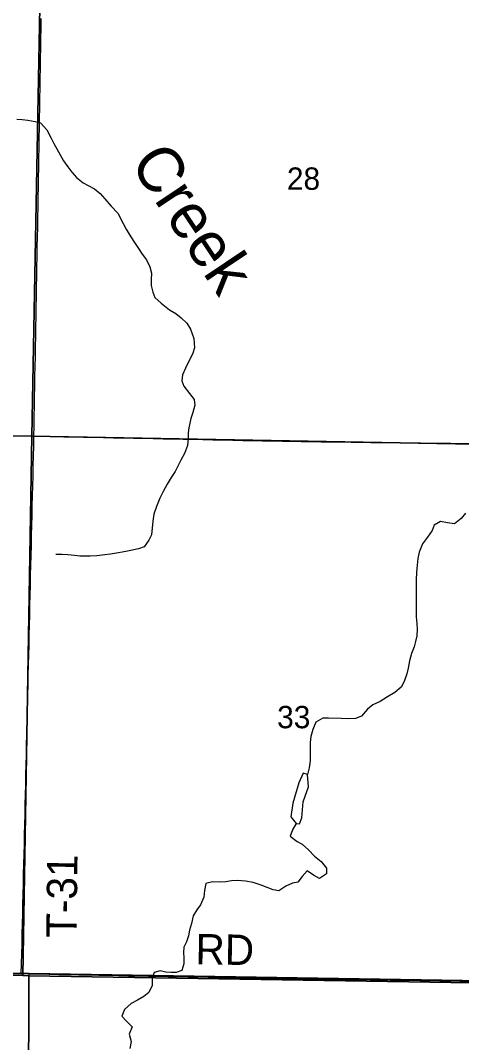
# Model space of a CAD drawing. Extents: x -11.1 to 34, y -3.9 to 22.
# Drawn here: x 3.372 to 4.199, y 18.172 to 20.086 of the extents above; entities that cross this region are included whole.
import ezdxf

# ---------------------------------------------------------------- set-up
doc = ezdxf.new("R2010")
doc.units = 0
for name, color, linetype in [('GM_X_Corporation', 7, 'Continuous'), ('GM_X_County_Road', 7, 'Continuous'), ('GM_X_County_Road_Text', 7, 'Continuous'), ('GM_X_Minor_Lake', 7, 'Continuous'), ('GM_X_Minor_River', 7, 'Continuous'), ('GM_X_Minor_River_Text', 7, 'Continuous'), ('GM_X_Section_Text', 7, 'Continuous'), ('GM_X_Township_Road', 7, 'Continuous'), ('GM_X_Township_Road_Text', 7, 'Continuous')]:
    doc.layers.add(name, color=color, linetype=linetype)

msp = doc.modelspace()

# ---------------------------------------------------------------- linework, layer by layer
at = {"layer": 'GM_X_Corporation'}
for points in [[(7.452, 20.9), (2.1, 20.9), (2.1, 18.3243), (2.3663, 18.3195), (2.386, 18.3192), (3.3765, 18.301), (3.3885, 18.301), (4.3933, 18.2849), (4.8079, 18.2783), (5.3973, 18.2661), (6.2873, 18.2553), (6.3214, 18.2549), (6.5234, 18.2515), (7.399, 18.2383)], [(7.399, 18.2383), (6.5234, 18.2515), (6.3214, 18.2549), (6.2873, 18.2553), (5.3973, 18.2661), (4.8079, 18.2783), (4.3933, 18.2849), (3.3885, 18.301), (3.3765, 18.301), (2.386, 18.3192), (2.3663, 18.3195), (2.1, 18.3243), (2.1, 15.3106)]]:
    msp.add_lwpolyline(points, dxfattribs=at)
for points in [[(3.4122, 20.3123), (3.3936, 19.3072), (2.3914, 19.3197), (2.4116, 20.3267)], [(4.4169, 20.2967), (4.3941, 19.2891), (3.3936, 19.3072), (3.4122, 20.3123)], [(2.3914, 19.3197), (3.3936, 19.3072), (3.3764, 18.2972), (2.3861, 18.3151), (2.3675, 18.3155)], [(4.3941, 19.2891), (4.3765, 18.281), (3.3877, 18.2966), (3.3764, 18.2972), (3.3936, 19.3072)], [(2.3861, 18.3151), (3.3764, 18.2972), (3.3877, 18.2966), (3.3852, 17.301), (2.3686, 17.3282)], [(4.3765, 18.281), (4.3966, 18.2798), (4.3866, 17.2855), (3.3852, 17.301), (3.3877, 18.2966)]]:
    msp.add_lwpolyline(points, close=True, dxfattribs=at)
at = {"layer": 'GM_X_County_Road'}
msp.add_line((3.3736, 18.3006), (3.3883, 18.3003), dxfattribs=at)
for points in [[(3.3618, 19.3079), (3.3795, 19.3076), (3.3972, 19.3073), (3.4158, 19.3069), (3.4345, 19.3066), (3.4531, 19.3062), (3.4718, 19.3058), (3.4904, 19.3054), (3.509, 19.3051), (3.5277, 19.3047), (3.5463, 19.3043), (3.5649, 19.3039), (3.5836, 19.3036), (3.6022, 19.3032), (3.6208, 19.3028), (3.6395, 19.3024), (3.6581, 19.3021), (3.6767, 19.3017), (3.6954, 19.3013), (3.714, 19.3009), (3.7326, 19.3006), (3.7513, 19.3002), (3.7699, 19.2998), (3.7885, 19.2994), (3.8072, 19.2991), (3.8258, 19.2987), (3.8445, 19.2983), (3.8631, 19.2979), (3.8807, 19.2976), (3.8984, 19.2972), (3.917, 19.297), (3.9357, 19.2968), (3.9543, 19.2965), (3.9729, 19.2963), (3.9916, 19.2961), (4.0102, 19.2959), (4.0289, 19.2956), (4.0475, 19.2954), (4.0661, 19.2952), (4.0848, 19.295), (4.1034, 19.2947), (4.1221, 19.2945), (4.1407, 19.2943), (4.1593, 19.294), (4.178, 19.2938), (4.1966, 19.2936), (4.2153, 19.2934)], [(3.3561, 18.3009), (3.3736, 18.3006)], [(3.3883, 18.3003), (3.407, 18.3), (3.4256, 18.2996), (3.4442, 18.2993), (3.4629, 18.2989), (3.4815, 18.2986), (3.5001, 18.2982), (3.5188, 18.2979), (3.5374, 18.2975), (3.556, 18.2972), (3.5747, 18.2968), (3.5933, 18.2965), (3.612, 18.2961), (3.6306, 18.2958), (3.6492, 18.2955), (3.6679, 18.2951), (3.6865, 18.2948), (3.7051, 18.2944), (3.7238, 18.2941), (3.7424, 18.2937), (3.761, 18.2934), (3.7797, 18.293), (3.7983, 18.2927), (3.8169, 18.2924), (3.8356, 18.292), (3.8542, 18.2917), (3.8664, 18.2914), (3.8786, 18.2912), (3.8972, 18.291), (3.9159, 18.2907), (3.9345, 18.2904), (3.9532, 18.2902), (3.9718, 18.2899), (3.9905, 18.2896), (4.0091, 18.2894), (4.0277, 18.2891), (4.0464, 18.2889), (4.065, 18.2886), (4.0837, 18.2883), (4.1023, 18.2881), (4.1209, 18.2878), (4.1396, 18.2876), (4.1582, 18.2873), (4.1769, 18.287), (4.1955, 18.2868), (4.2141, 18.2865)]]:
    msp.add_lwpolyline(points, dxfattribs=at)
at = {"layer": 'GM_X_Minor_Lake'}
for points in [[(3.9099, 18.6738), (3.902, 18.676), (3.8935, 18.6578), (3.8826, 18.6201), (3.879, 18.5946), (3.8889, 18.5816), (3.8948, 18.5813)], [(3.8948, 18.5813), (3.8996, 18.5922), (3.902, 18.6226), (3.9117, 18.6505), (3.9099, 18.6738)]]:
    msp.add_lwpolyline(points, dxfattribs=at)
at = {"layer": 'GM_X_Minor_River'}
for points in [[(3.3649, 19.9007), (3.3755, 19.9001), (3.3857, 19.8991), (3.3997, 19.8968), (3.4095, 19.8939), (3.4214, 19.8808), (3.4297, 19.8654), (3.4348, 19.8554), (3.4436, 19.8396), (3.4527, 19.8231), (3.4608, 19.8115), (3.4685, 19.8014), (3.477, 19.7917), (3.4893, 19.7816), (3.499, 19.7768), (3.511, 19.7704), (3.5215, 19.7615), (3.53, 19.7518), (3.5422, 19.7378), (3.5548, 19.7246), (3.5646, 19.7058), (3.5704, 19.695), (3.5755, 19.6854), (3.5843, 19.6719), (3.5931, 19.6588), (3.6004, 19.648), (3.6085, 19.6372), (3.6143, 19.6241), (3.6175, 19.6123), (3.6168, 19.6005), (3.6169, 19.5895)], [(3.6169, 19.5895), (3.6201, 19.5769), (3.624, 19.5669), (3.6355, 19.5564), (3.6516, 19.5439), (3.6632, 19.5368), (3.6732, 19.5289), (3.6836, 19.5188), (3.691, 19.5076), (3.697, 19.49), (3.6985, 19.4725), (3.6949, 19.4624), (3.6813, 19.4346), (3.6757, 19.4218), (3.6747, 19.4108), (3.6783, 19.4008), (3.689, 19.3873), (3.6978, 19.3757), (3.6987, 19.3654), (3.695, 19.3514), (3.6913, 19.3405), (3.6875, 19.3231), (3.6866, 19.3133), (3.6863, 19.3027), (3.6849, 19.2898), (3.6796, 19.2747), (3.6725, 19.262), (3.6669, 19.2511), (3.6618, 19.2413), (3.6547, 19.2301), (3.6472, 19.2173), (3.6393, 19.2035), (3.6333, 19.1911), (3.6269, 19.1757), (3.622, 19.161), (3.6202, 19.1481), (3.6174, 19.1223), (3.6126, 19.1126), (3.604, 19.0998), (3.5933, 19.0963), (3.5791, 19.0932), (3.5692, 19.0912), (3.5559, 19.0888), (3.5407, 19.0865), (3.5304, 19.0848), (3.5152, 19.0829), (3.5027, 19.0824), (3.4932, 19.0823), (3.4833, 19.0825), (3.4735, 19.0835), (3.4606, 19.0849), (3.4504, 19.0855), (3.4386, 19.0858)], [(4.2059, 19.163), (4.1981, 19.1533), (4.1857, 19.143), (4.1725, 19.1452), (4.1596, 19.1477), (4.1473, 19.1408), (4.1437, 19.1306), (4.1351, 19.1183), (4.1253, 19.1056), (4.1196, 19.0898), (4.1167, 19.0781), (4.1153, 19.0656), (4.1142, 19.0519), (4.1135, 19.0387), (4.1136, 19.0254), (4.1134, 19.0159), (4.1135, 19.0026), (4.1136, 18.9931), (4.1137, 18.9794), (4.1139, 18.9688), (4.1151, 18.9566), (4.1156, 18.9452), (4.1149, 18.9334), (4.1124, 18.9225), (4.1099, 18.9127), (4.1051, 18.9002), (4.101, 18.8863), (4.0984, 18.8727), (4.0959, 18.8621), (4.0914, 18.8478), (4.0855, 18.8373), (4.0739, 18.8273), (4.06, 18.8192), (4.0465, 18.8104), (4.0327, 18.8043), (4.0223, 18.7962), (4.0114, 18.7828), (3.9999, 18.7785)], [(3.9999, 18.7785), (3.9866, 18.7776), (3.973, 18.7787), (3.9491, 18.7793), (3.9389, 18.7791), (3.9254, 18.7718), (3.9198, 18.7579), (3.9161, 18.7447), (3.9151, 18.7333), (3.9148, 18.7231), (3.9149, 18.7117), (3.915, 18.6992), (3.9129, 18.6863), (3.9099, 18.6738)], [(3.8889, 18.5816), (3.8821, 18.57), (3.8777, 18.558), (3.8904, 18.5482), (3.9001, 18.543), (3.912, 18.5325), (3.9231, 18.5205), (3.9354, 18.5107), (3.9454, 18.4983), (3.9455, 18.4877), (3.9328, 18.4785), (3.9212, 18.4848), (3.9092, 18.4934), (3.8999, 18.4823), (3.8921, 18.4722), (3.8822, 18.4698), (3.8695, 18.4643), (3.8564, 18.4559), (3.8458, 18.4577), (3.8346, 18.4617), (3.8233, 18.4662), (3.8082, 18.4711), (3.7939, 18.4737), (3.7791, 18.4748), (3.7673, 18.4747), (3.757, 18.4723), (3.7456, 18.4718), (3.732, 18.4728), (3.7194, 18.4697), (3.7168, 18.4565), (3.7154, 18.444), (3.7094, 18.4297), (3.7027, 18.42), (3.696, 18.4091), (3.6923, 18.3947), (3.689, 18.3819), (3.6869, 18.3717), (3.6832, 18.3604), (3.678, 18.3503), (3.6774, 18.34), (3.6783, 18.3301), (3.6785, 18.3187), (3.6744, 18.3067), (3.6641, 18.3027), (3.6542, 18.3026), (3.6444, 18.3035), (3.6338, 18.3061), (3.6223, 18.3029), (3.6186, 18.2908), (3.6187, 18.2783), (3.6128, 18.2651), (3.6031, 18.2581), (3.5916, 18.2512), (3.5793, 18.245), (3.5669, 18.2335), (3.5617, 18.2211), (3.571, 18.2114), (3.5814, 18.2013), (3.5757, 18.187), (3.5792, 18.1736), (3.577, 18.1604)]]:
    msp.add_lwpolyline(points, dxfattribs=at)
at = {"layer": 'GM_X_Township_Road'}
msp.add_line((3.3883, 18.3003), (3.3736, 18.3006), dxfattribs=at)
for points in [[(3.3736, 18.3006), (3.3741, 18.3192), (3.3745, 18.3379), (3.375, 18.3565), (3.3754, 18.3751), (3.3758, 18.3938), (3.3762, 18.4124), (3.3767, 18.431), (3.3771, 18.4497), (3.3775, 18.4683), (3.378, 18.4869), (3.3784, 18.5056), (3.3788, 18.5242), (3.3793, 18.5428), (3.3797, 18.5615), (3.3801, 18.5801), (3.3806, 18.5987), (3.381, 18.6174), (3.3814, 18.636), (3.3819, 18.6547), (3.3823, 18.6733), (3.3827, 18.6919), (3.3832, 18.7106), (3.3836, 18.7292), (3.384, 18.7478), (3.3845, 18.7665), (3.3849, 18.7851), (3.3851, 18.7947), (3.3853, 18.8043), (3.3858, 18.823), (3.3862, 18.8416), (3.3867, 18.8602), (3.3871, 18.8789), (3.3875, 18.8975), (3.388, 18.9161), (3.3884, 18.9348), (3.3889, 18.9534), (3.3893, 18.972), (3.3897, 18.9907), (3.3902, 19.0093), (3.3906, 19.0279), (3.3911, 19.0466), (3.3915, 19.0652), (3.392, 19.0838), (3.3924, 19.1025), (3.3928, 19.1211), (3.3933, 19.1398), (3.3937, 19.1584), (3.3942, 19.177), (3.3946, 19.1957), (3.395, 19.2143), (3.3955, 19.2329), (3.3959, 19.2516), (3.3963, 19.2702), (3.3968, 19.2887), (3.3972, 19.3073), (3.3976, 19.3259), (3.3979, 19.3446), (3.3982, 19.3632), (3.3986, 19.3819), (3.3989, 19.4005), (3.3992, 19.4191), (3.3996, 19.4378), (3.3999, 19.4564), (3.4002, 19.4751), (3.4006, 19.4937), (3.4009, 19.5123), (3.4012, 19.531), (3.4016, 19.5496), (3.4019, 19.5683), (3.4022, 19.5869), (3.4026, 19.6056), (3.4029, 19.6242), (3.4033, 19.6428), (3.4036, 19.6615), (3.4039, 19.6801), (3.4043, 19.6988), (3.4046, 19.7174), (3.4049, 19.736), (3.4053, 19.7547), (3.4056, 19.7733), (3.4059, 19.7916), (3.4062, 19.8099), (3.4066, 19.8285), (3.4069, 19.8471), (3.4072, 19.8658), (3.4075, 19.8844), (3.4079, 19.9031), (3.4082, 19.9217), (3.4085, 19.9403), (3.4088, 19.959), (3.4092, 19.9776), (3.4095, 19.9963), (3.4098, 20.0149), (3.4101, 20.0336), (3.4104, 20.0522), (3.4108, 20.0708), (3.4111, 20.0895)], [(3.3878, 18.16), (3.3879, 18.1786), (3.388, 18.1972), (3.388, 18.2159), (3.3881, 18.2345), (3.3882, 18.2532), (3.3882, 18.2718), (3.3883, 18.3003)]]:
    msp.add_lwpolyline(points, dxfattribs=at)

# ---------------------------------------------------------------- texts
at = {"layer": 'GM_X_County_Road_Text'}
msp.add_text('RD', height=0.05682, rotation=359.0128, dxfattribs=at).set_placement((3.6997, 18.3183))
at = {"layer": 'GM_X_Minor_River_Text'}
msp.add_text('Creek', height=0.08523, rotation=303.7158, dxfattribs=at).set_placement((3.5756, 19.8187))
at = {"layer": 'GM_X_Section_Text'}
for s, p in [('28', (3.8714, 19.7686)), ('33', (3.8531, 18.7602))]:
    msp.add_text(s, height=0.04186, rotation=0, dxfattribs=at).set_placement(p)
at = {"layer": 'GM_X_Township_Road_Text'}
msp.add_text('T-31', height=0.05682, rotation=89.2931, dxfattribs=at).set_placement((3.4771, 18.3673))

doc.saveas('drawing.dxf')
